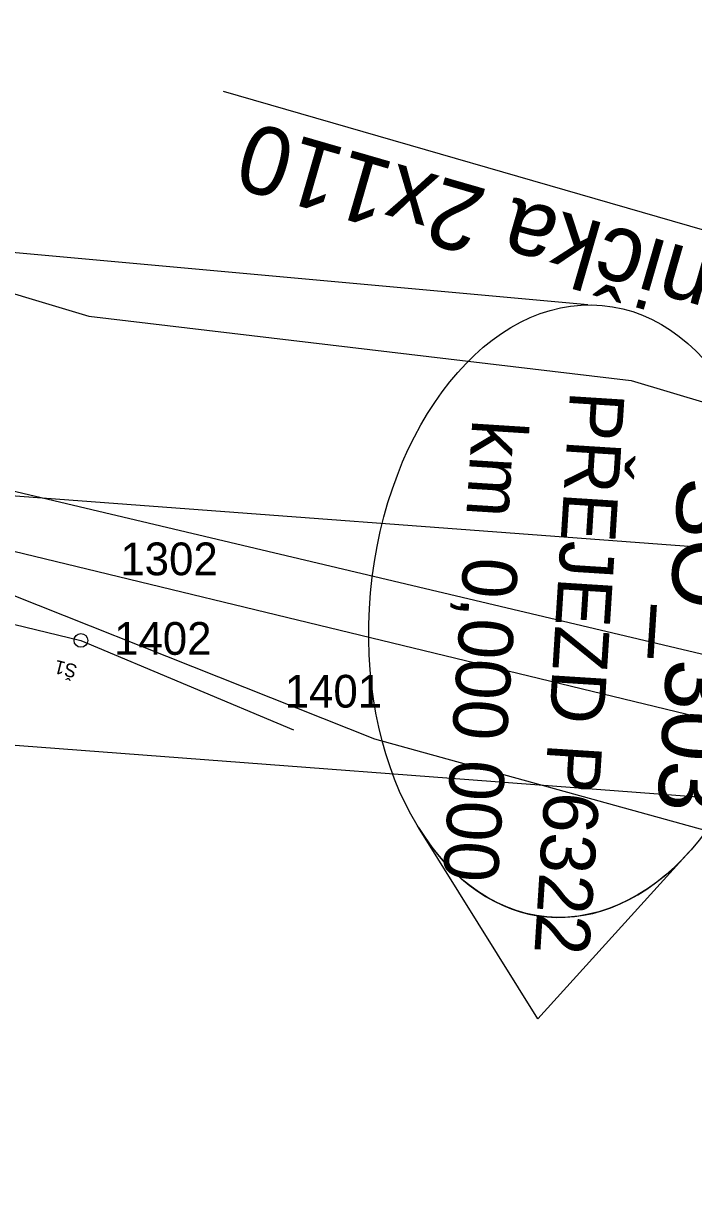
# Model space of a CAD drawing. Extents: x -748344 to -743169, y -1131966 to -1127091.
# Drawn here: x -747581.68 to -747557.13, y -1131732.17 to -1131689.39 of the extents above; entities that cross this region are included whole.
import ezdxf

# ---------------------------------------------------------------- set-up
doc = ezdxf.new("R2010")
doc.units = 0
for name, color, linetype in [('_Násyp', 7, 'Continuous'), ('_Zabezpečovací zařízení_trasa', 7, 'Continuous'), ('bublina_fialová_čára_tenká', 7, 'Continuous'), ('bublina_růžová_230_čára_tučná', 7, 'Continuous'), ('křížky', 7, 'Continuous'), ('Nový stav', 7, 'Continuous'), ('SMEROVE_A_VYSKOVE_VYROVNANI', 7, 'Continuous'), ('TRATIVOD', 7, 'Continuous'), ('TRATIVOD_POP', 7, 'Continuous'), ('Vrstva 53', 7, 'Continuous'), ('Vrstva 60', 7, 'Continuous')]:
    doc.layers.add(name, color=color, linetype=linetype)

# ---------------------------------------------------------------- blocks, each defined once
blk = doc.blocks.new('POINT_DISPLAY')
blk.add_line((0, 0), (0, 0))

msp = doc.modelspace()

# ---------------------------------------------------------------- linework, layer by layer
at = {"layer": '_Zabezpečovací zařízení_trasa'}
msp.add_lwpolyline([(-747299.39, -1131774.358), (-747312.964, -1131771.536), (-747335.194, -1131765.862), (-747431.496, -1131743.033), (-747485.589, -1131729.823), (-747529.872, -1131718.897), (-747616.745, -1131698.315), (-747822.016, -1131648.41), (-747861.482, -1131639.038), (-748013.304, -1131601.999), (-748116.903, -1131577.077), (-748210.219, -1131554.485), (-748277.301, -1131538.228)], dxfattribs=at)
at = {"layer": 'bublina_fialová_čára_tenká'}
for p, q in [((-747560.999, -1131699.707), (-747593.352, -1131696.768)), ((-747518.052, -1131711.518), (-747594.166, -1131705.802)), ((-747545.254, -1131718.632), (-747593.043, -1131715.025))]:
    msp.add_line(p, q, dxfattribs=at)
at = {"layer": 'bublina_růžová_230_čára_tučná'}
for p, q in [((-747562.835, -1131725.871), (-747567.202, -1131718.866)), ((-747562.835, -1131725.871), (-747567.202, -1131718.866)), ((-747557.287, -1131719.758), (-747562.835, -1131725.871)), ((-747557.287, -1131719.758), (-747562.835, -1131725.871))]:
    msp.add_line(p, q, dxfattribs=at)
msp.add_ellipse((-747561.49, -1131710.931), major_axis=(1.008, 11.205), ratio=0.666667, dxfattribs=at)
msp.add_ellipse((-747561.49, -1131710.931), major_axis=(-1.008, -11.206), ratio=0.666473, start_param=5.557317, end_param=7.009053, dxfattribs=at)
at = {"layer": 'Nový stav'}
msp.add_line((-747548.877, -1131699.252), (-747574.351, -1131691.884), dxfattribs=at)
at = {"layer": 'SMEROVE_A_VYSKOVE_VYROVNANI'}
msp.add_lwpolyline([(-747586.682, -1131707.613), (-747539.653, -1131718.994)], dxfattribs=at)
at = {"layer": 'TRATIVOD'}
msp.add_lwpolyline([(-747602.124, -1131706.551), (-747591.472, -1131709.129), (-747579.575, -1131712.008), (-747571.785, -1131715.287)], dxfattribs=at)
msp.add_circle((-747579.575, -1131712.008), 0.25, dxfattribs=at)
at = {"layer": 'Vrstva 53'}
msp.add_lwpolyline([(-747431.62, -1131748.34), (-747522.4, -1131724.74), (-747551.8, -1131720.33), (-747568.8, -1131715.62), (-747587.81, -1131708.07), (-747592.13, -1131708.07), (-747590.72, -1131696.79), (-747584.22, -1131698.64), (-747579.28, -1131700.12), (-747559.41, -1131702.48), (-747542.02, -1131707.68), (-747515.95, -1131716.72), (-747422.18, -1131737.69)], dxfattribs=at)
at = {"layer": 'Vrstva 60'}
for p, q in [((-747578.964, -1131709.481), (-747578.964, -1131709.481)), ((-747579.575, -1131712.008), (-747579.575, -1131712.008)), ((-747571.785, -1131715.287), (-747571.785, -1131715.287))]:
    msp.add_line(p, q, dxfattribs=at)

# ---------------------------------------------------------------- block references
at = {"layer": 'křížky', "xscale": 10, "yscale": 10, "rotation": 61.14491455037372}
for p in [(-747578.964, -1131709.481), (-747579.575, -1131712.008), (-747571.785, -1131715.287)]:
    msp.add_blockref('POINT_DISPLAY', p, dxfattribs=at)

# ---------------------------------------------------------------- texts
at = {"layer": '_Násyp'}
for s, height, p in [('PŘEJEZD P6322', 2, (-747561.647, -1131702.835)), ('km  0,000 000', 2, (-747565.229, -1131703.875)), ('SO_303', 2.5, (-747557.676, -1131705.974))]:
    msp.add_text(s, height=height, rotation=266.3528, dxfattribs=at).set_placement(p)
at = {"layer": 'Nový stav'}
msp.add_text('chránička 2x110', height=2.5, rotation=163.8668, dxfattribs=at).set_placement((-747549.973, -1131699.739))
at = {"layer": 'TRATIVOD_POP'}
msp.add_text('Š1', height=0.5, rotation=166, dxfattribs=at).set_placement((-747579.672, -1131712.914))
at = {"layer": 'Vrstva 60'}
for s, p in [('1302', (-747578.129, -1131709.618)), ('1402', (-747578.358, -1131712.534)), ('1401', (-747572.107, -1131714.468))]:
    msp.add_text(s, height=1.2, dxfattribs=at).set_placement(p)

doc.saveas('drawing.dxf')
